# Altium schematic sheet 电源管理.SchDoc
size A4
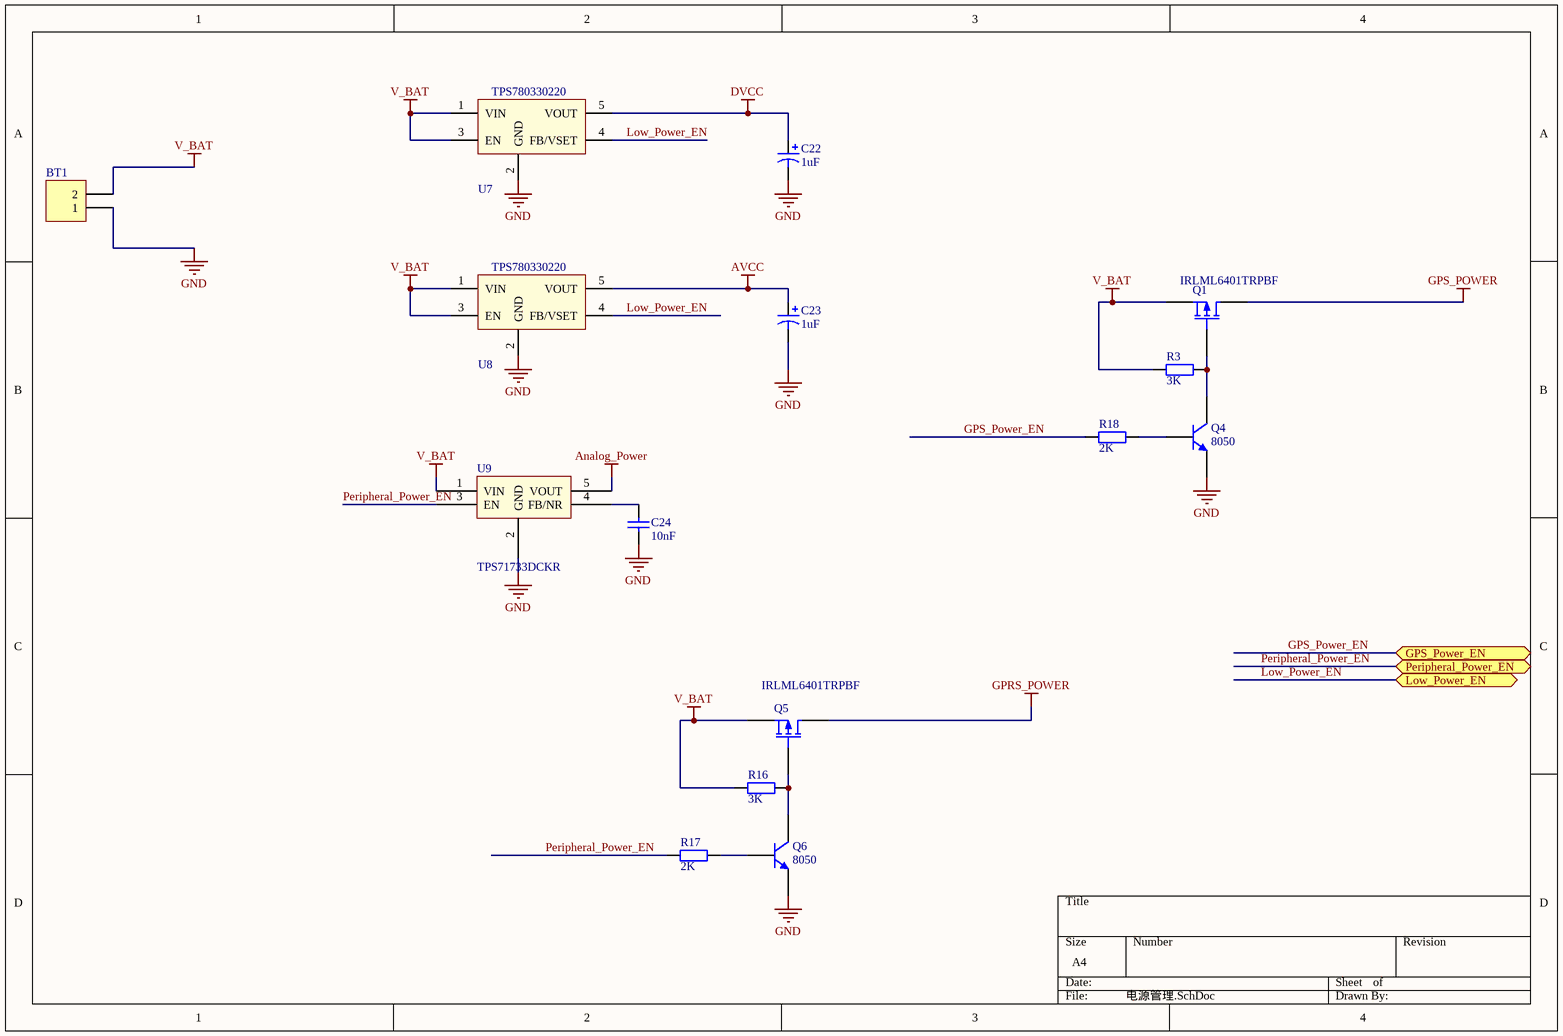
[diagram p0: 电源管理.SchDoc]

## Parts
BT1  (no value)  [XH2.54-2P]
C22  value 1uF  [1206C]
C23  value 1uF  [1206C]
C24  value 10nF  [0805C]
Q1  IRLML6401TRPBF  [SOT23-3]
Q4  8050  [SOT23-3]
Q5  IRLML6401TRPBF  [SOT23-3]
Q6  8050  [SOT23-3]
R3  value 3K  [0805R]
R16  value 3K  [0805R]
R17  value 2K  [0805R]
R18  value 2K  [0805R]
U7  TPS780330220  [SOT23-5]
U8  TPS780330220  [SOT23-5]
U9  TPS71733DCKR  [SC70-5]

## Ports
GPS_Power_EN, Low_Power_EN, Peripheral_Power_EN

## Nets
Analog_Power: U9.5(VOUT)
AVCC: C23.1 U8.5(VOUT)
DVCC: C22.1 U7.5(VOUT)
GND: BT1.1 C22.2 C23.2 C24.1 Q4.2(E) Q6.2(E) U7.2(GND) U8.2(GND) U9.2(GND)
GPRS_POWER: Q5.3(D)
GPS_POWER: Q1.3(D)
V_BAT: BT1.2 Q1.2(S) Q5.2(S) R3.1 R16.1 U7.1(VIN) U7.3(EN) U8.1(VIN) U8.3(EN) U9.1(VIN)
GPS_Power_EN: R18.1 ; port GPS_Power_EN
Low_Power_EN: U7.4(FB/VSET) U8.4(FB/VSET) ; port Low_Power_EN
Peripheral_Power_EN: R17.1 U9.3(EN) ; port Peripheral_Power_EN
NetC24_2: C24.2 U9.4(FB/NR)
NetQ1_1: Q1.1(G) Q4.3(C) R3.2
NetQ4_1: Q4.1(B) R18.2
NetQ5_1: Q5.1(G) Q6.3(C) R16.2
NetQ6_1: Q6.1(B) R17.2

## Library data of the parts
BT1 = Header 2: Header, 2-Pin
C22 C23 = Cap Pol1: 钽电容
C24 = Cap: 瓷片电容
Q1 Q5 = IRLML6401TRPBF: 小功率MOSFET
Q4 Q6 = NPN_SOT: NPN型贴片三极管
R3 R16-R18 = Res2: 碳膜电阻
U7 U8 = TPS780220330: 线性稳压器
U9 = TPS71701: 高PSRR线性稳压器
